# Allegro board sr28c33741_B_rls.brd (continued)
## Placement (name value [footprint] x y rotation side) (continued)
L263  2.7NH  [IND1005-HT0_6_HD]  59.09 13.08 90 top
L270  3.4NH  [IND1005-HT0_6_HD]  60.33 14.34 90 top
L271  0  [RES0402-HT0_4_HD]  61.44 14.73 0 top
L277  270NH  [INDP0402-HT0_55_HD]  63.98 15.95 0 top
L279  22NH  [IND0201-HT0_35_HD]  64.92 14.92 90 top
L301  56nH  [IND0201-HT0_33_HD]  60.02 34.46 0 top
L304  0  [RES0402-HT0_4_HD]  61.67 33.52 90 top
L305  2.5NH  [IND1005-HT0_6_HD]  60.92 34.59 90 top
L401  56nH  [IND0201-HT0_33_HD]  10.79 31.26 180 top
L404  2.2NH  [IND1005-HT0_6_HD]  8.88 32.8 180 top
L405  1e-006 uF  [CAP0402-HT0_55_HD]  8.88 33.57 180 top
L2200  0.47 uH  [IND2X1_6_PS1_55_HD]  26.07 58.91 0 top
L2201  0.47 uH  [IND2X1_6_PS1_55_HD]  26.73 60.96 0 top
L2202  0.47 uH  [IND2X1_6_PS1_55_HD]  24.07 61.76 0 top
L2203  1 uH  [IND2X1_6_PS1_4_HD]  23 52.29 270 top
L2204  1 uH  [IND2X1_6_PS1_4_HD]  26.83 53.45 0 top
L2205  1 uH  [IND2X1_6_PS1_4_HD]  25.98 56.86 0 top
L2270  1 uH  [IND2X1_6_PS1_4_HD]  8.54 59.75 270 top
L2300  0.47 uH  [IND2X1_6_PS1_55_HD]  32.66 43.26 90 top
L2301  0.47 uH  [IND2X1_6_PS1_55_HD]  42.2 43.65 0 top
L2302  0.47 uH  [IND2X1_6_PS1_55_HD]  39.06 45.94 90 top
L2303  0.47 uH  [IND2X1_6_PS1_55_HD]  36.29 45.92 90 top
L2304  0.47 uH  [IND2X1_6_PS1_55_HD]  34.24 45.91 90 top
L2400  1 uH  [IND2X1_6_PS1_4_HD]  16.4 60.73 90 top
L2440  0.47 uH  [IND2X1_6_PS1_55_HD]  42.45 40.41 270 top
L2501  4.7uH  [IND2_5X2_PS1_95_HD]  34.15 35.63 180 top
L2502  4.7uH  [IND2_5X2_PS1_95_HD]  39.41 35.49 0 top
L2503  4.7uH  [IND2_5X2_PS1_95_HD]  42.3 36.4 270 top
L2560  0.47 uH  [IND2X1_6_PS1_55_HD]  25.4 51.33 0 top
L2570  0.47 uH  [IND2X1_6_PS1_55_HD]  57.13 48.33 180 top
L3201  1PF  [CAP0201-HT0_33_HD]  26.91 36.75 270 top
L4041  3NH  [IND0201-HT0_35_HD]  46.76 35.01 270 top
L4042  8.2NH  [IND0201-HT0_35_HD]  45.76 32.95 90 top
L4046  0.039 uH  [IND0201-HT0_35_HD]  47.8 31.92 180 top
L4048  0.039 uH  [IND0201-HT0_35_HD]  47.79 30.49 180 top
L4051  3NH  [IND0201-HT0_35_HD]  56.38 27.93 90 top
L4052  8.2NH  [IND0201-HT0_35_HD]  58.11 27.19 270 top
L4056  0.039 uH  [IND0201-HT0_35_HD]  58.51 24.44 180 top
L4058  0.039 uH  [IND0201-HT0_35_HD]  58.74 23.02 180 top
L4061  9.1NH  [IND0201-HT0_35_HD]  60.09 27.54 0 top
L4062  9.1NH  [IND0201-HT0_35_HD]  60.74 25.13 90 top
L4066  0.039 uH  [IND0201-HT0_35_HD]  60.54 24.19 270 top
L4068  0.039 uH  [IND0201-HT0_35_HD]  59.83 22.99 0 top
L4071  9.1NH  [IND0201-HT0_35_HD]  53.35 31.76 0 top
L4072  9.1NH  [IND0201-HT0_35_HD]  51.8 30.1 90 top
L4076  0.039 uH  [IND0201-HT0_35_HD]  49.65 30.55 270 top
L4078  0.039 uH  [IND0201-HT0_35_HD]  48.96 30.56 270 top
L4120  1 uH  [IND2X1_6_PS1_4_HD]  62.63 49.42 90 top
L4150  82NH  [IND1005-HT0_6_HD]  60.66 57.45 180 top
L4160  82NH  [IND1005-HT0_6_HD]  58.93 56.99 90 top
L4600  1 uH  [IND2X1_6_PS1_4_HD]  8.99 20.66 0 top
L4610  0.12 uH  [IND0603_HD]  9.81 10.22 221 top
L4611  0.12 uH  [IND0603_HD]  8.93 4.72 170 top
L4670  18nH  [IND0603_SZ1_65X0_99-HT1_HD]  34.69 12.06 270 bottom
L4671  18nH  [IND0603_SZ1_65X0_99-HT1_HD]  39.59 12.06 270 bottom
L6292  0.47 uH  [IND0603-HT0_95_HD]  14.42 52.03 180 top
L6400  1 uH  [IND2X1_6_PS1_4_HD]  11.16 25.88 180 top
L6401  160nH  [IND0603_HD]  15.82 16.54 270 top
L6402  160nH  [IND0603_HD]  16.97 16.54 270 top
L7001  9.1NH  [IND0201-HT0_35_HD]  28.25 16.18 270 top
L7004  .5PF  [CAP0201-HT0_33_HD]  27.7 13.48 90 top
L7030  3.6NH  [IND0201-HT0_35_HD]  40.96 14.89 180 top
L7031  3.3 NH  [IND0201-HT0_35_HD]  39.09 15.37 270 top
L7051  .5PF  [CAP0201-HT0_33_HD]  10.14 28.87 90 top
L7056  .5PF  [CAP0201-HT0_33_HD]  9.88 31.86 180 top
L7111  18NH  [IND0201-HT0_35_HD]  53.52 19.72 180 top
L7113  0.027 uH  [IND0201-HT0_35_HD]  53.52 20.82 180 top
L7115  18NH  [IND0201-HT0_35_HD]  53.52 21.85 180 top
L7127  1NH  [IND0201-HT0_35_HD]  49.25 15.84 180 top
L7130  1.8PF  [CAP0201-HT0_33_HD]  49.44 17.09 180 top
L7131  8.2PF  [CAP0201-HT0_33_HD]  49.44 16.59 0 top
L7132  12NH  [IND0201-HT0_35_HD]  50.72 16.05 90 top
L7140  18NH  [IND0201-HT0_35_HD]  45.77 17.11 0 top
L7142  18NH  [IND0201-HT0_35_HD]  50.2 16.05 90 top
L7144  18NH  [IND0201-HT0_35_HD]  39.89 14.69 180 top
L7166  4.3NH  [IND0201-HT0_35_HD]  33.05 25.71 270 top
L7171  18NH  [IND0201-HT0_35_HD]  36.44 14.02 90 top
L7172  .5PF  [CAP0201-HT0_33_HD]  38.83 14.63 180 top
L7173  18NH  [IND0201-HT0_35_HD]  36.64 15.73 180 top
L7180  18NH  [IND0201-HT0_35_HD]  37.68 15.75 180 top
L7183  1NH  [IND0201-HT0_35_HD]  37.94 14.96 270 top
L7184  3NH  [IND0201-HT0_35_HD]  32.09 21.46 270 top
L7219  18NH  [IND0201-HT0_35_HD]  27.72 25.9 180 top
L7231  3.3PF  [CAP0201-HT0_33_HD]  47.69 24.33 270 top
L7232  0  [RES0201-HT0_28_HD]  46.98 24.18 0 top
L7233  15NH  [IND0201-HT0_35_HD]  43.18 20.03 90 top
L7236  6.2NH  [IND0201-HT0_35_HD]  43.93 20.2 0 top
L7237  100PF  [CAP0201-HT0_33_HD]  44.66 19.97 90 top
L7239  8.2NH  [IND0201-HT0_35_HD]  44.55 19.2 180 top
L7240  15NH  [IND0201-HT0_35_HD]  44.46 23.41 270 top
L7260  2.2PF  [CAP0201-HT0_33_HD]  48.2 25.28 270 top
L7262  0.047 uH  [IND0201-HT0_35_HD]  46.48 25.26 270 top
L7263  12NH  [IND0201-HT0_35_HD]  45.02 26.3 0 top
L7265  0.033 uH  [IND0201-HT0_35_HD]  45.93 27.01 180 top
L7267  8.2NH  [IND0201-HT0_35_HD]  47.38 26.76 180 top
L7268  0.047 uH  [IND0201-HT0_35_HD]  43.29 24.71 270 top
L7274  15NH  [IND0201-HT0_35_HD]  28.63 25.89 0 top
L7301  22NH  [IND0201-HT0_35_HD]  31.81 20.57 180 top
L7302  0  [RES0201-HT0_28_HD]  31.68 19.75 270 top
L7303  3.6NH  [IND0201-HT0_35_HD]  32.45 15.24 0 top
L7306  0  [RES0201-HT0_28_HD]  30.21 30.91 90 top
L7311  18NH  [IND0201-HT0_35_HD]  31.94 18.94 0 top
L7313  6.2NH  [IND0201-HT0_35_HD]  35.15 13.26 180 top
L7317  3.6NH  [IND0201-HT0_35_HD]  35.71 15.74 180 top
L7318  0  [RES0201-HT0_28_HD]  34.77 15.74 180 top
L7326  4.7NH  [IND0201-HT0_35_HD]  28.97 30.94 180 top
L7328  1.6NH  [IND0201-HT0_35_HD]  28.85 31.67 270 top
L7329  2.4NH  [IND0201-HT0_35_HD]  29.22 32.78 270 top
L7331  1NH  [IND0201-HT0_35_HD]  29.81 30.19 180 top
L7332  6.8NH  [IND0201-HT0_35_HD]  31.32 30.18 180 top
L7333  .9NH  [IND0201-HT0_35_HD]  28.88 29.97 180 top
L7334  2NH  [IND0201-HT0_35_HD]  29.73 29.2 90 top
L7335  6.8NH  [IND0201-HT0_35_HD]  26.77 29.1 180 top
L7336  1NH  [IND0201-HT0_35_HD]  26.1 29.76 90 top
L7350  18NH  [IND0201-HT0_35_HD]  39.83 22 180 top
L7352  9.1NH  [IND0201-HT0_35_HD]  40.59 21.69 270 top
L7354  9.1NH  [IND0201-HT0_35_HD]  39.83 18.65 0 top
L7367  1.5NH  [IND0201-HT0_35_HD]  28.63 28.18 90 top
L7368  2.7NH  [IND0201-HT0_35_HD]  28.11 29.69 90 top
L7371  3.3 NH  [IND0201-HT0_35_HD]  27.71 28.07 90 top
L7505  0.039 uH  [IND0201-HT0_35_HD]  16.05 24.76 270 top
L7516  4.7NH  [IND0201-HT0_35_HD]  22.67 23.63 270 top
L7525  22NH  [IND0201-HT0_35_HD]  42.65 31.6 0 top
L7601  3.9NH  [IND0201-HT0_35_HD]  18.77 28.3 0 top
L7603  .9NH  [IND0201-HT0_35_HD]  21.62 29.85 0 top
L7611  2.7NH  [IND0201-HT0_35_HD]  21.26 25.72 90 top
L7612  2.7NH  [IND0201-HT0_35_HD]  24.69 28.46 90 top
L7614  1.5NH  [IND0201-HT0_35_HD]  24.41 29.41 90 top
L7616  1NH  [IND0201-HT0_35_HD]  21.54 30.48 0 top
L7621  4.3NH  [IND0201-HT0_35_HD]  18.21 26.8 270 top
L7623  4.3NH  [IND0201-HT0_35_HD]  19.7 25.82 90 top
L7626  4.7NH  [IND0201-HT0_35_HD]  21.54 30.98 0 top
L7627  9.1NH  [IND0201-HT0_35_HD]  42.93 29.86 90 top
L7629  4.3NH  [IND0201-HT0_35_HD]  19.87 28.19 180 top
L7630  4.3NH  [IND0201-HT0_35_HD]  23.86 27.47 90 top
L7631  10NH  [IND0201-HT0_35_HD]  21.29 27.23 90 top
L7647  15NH  [IND0201-HT0_35_HD]  20.55 29.13 90 top
L7648  15NH  [IND0201-HT0_35_HD]  17.97 29.47 90 top
L7703  18NH  [IND0201-HT0_35_HD]  14.64 34.23 180 top
L7708  15NH  [IND0201-HT0_35_HD]  15.57 34.21 0 top
L7716  1NH  [IND0201-HT0_35_HD]  15.83 26.84 0 top
L7717  1NH  [IND0201-HT0_35_HD]  13.44 29.84 0 top
L7721  15NH  [IND0201-HT0_35_HD]  12.8 31.98 0 top
L7722  15NH  [IND0201-HT0_35_HD]  12.71 34.25 0 top
L7801  6.8NH  [IND0201-HT0_35_HD]  39.84 28.58 270 top
L7820  3NH  [IND0201-HT0_35_HD]  34.6 28.93 0 top
L7821  9.1NH  [IND0201-HT0_35_HD]  35.6 31.27 0 top
L7825  1NH  [IND0201-HT0_35_HD]  23.91 29.41 90 top
L7831  3.3 NH  [IND0201-HT0_35_HD]  38.98 31.02 270 top
L7832  1.8PF  [CAP0201-HT0_33_HD]  21.82 29.13 90 top
L7833  3.3 NH  [IND0201-HT0_35_HD]  36.76 30.34 90 top
L7834  15PF  [CAP0201-HT0_33_HD]  21.82 28.21 270 top
L8200  1uH  [IND2_5X2_PS1_95_HD]  25 17.05 180 top
L8201  1 uH  [IND2X1_6_PS1_4_HD]  19.93 18.77 270 top
L8501  9.1NH  [IND0201-HT0_35_HD]  24.86 24.59 270 top
L8502  8.2NH  [IND0201-HT0_35_HD]  23.73 24.03 180 top
L8503  7.5NH  [IND0201-HT0_35_HD]  22.49 25.87 180 top
L8504  6.2NH  [IND0201-HT0_35_HD]  20.61 31.81 0 top
L8516  2.2PF  [CAP0201-HT0_33_HD]  20.87 34.93 180 top
L8518  9.1NH  [IND0201-HT0_35_HD]  21.23 33.38 270 top
L8519  9.1NH  [IND0201-HT0_35_HD]  20.64 34.22 270 top
M001  -  [MECH0_7X4_5_HD]  48.15 46.18 90 top
M002  -  [MECH0_7X2_83_HD]  3.91 59.15 180 top
M003  -  [MECH0_7X2_83_HD]  4.21 53.9 180 top
M004  -  [MECH0_7X4_5_HD]  9.34 49.53 90 top
M005  -  [MECH0_7X2_83_HD]  17.12 49.53 90 top
M006  -  [MECH0_7X4_5_HD]  16.14 63.32 270 top
M007  -  [MECH0_7X4_5_HD]  22.84 63.32 90 top
M008  -  [MECH0_7X4_5_HD]  31.65 63.32 90 top
M009  -  [MECH0_7X4_5_HD]  38.65 63.32 90 top
M010  -  [MECH0_7X4_5_HD]  45.99 63.32 90 top
M011  -  [MECH0_7X2_83_HD]  44.05 37.26 0 top
M012  -  [MECH0_7X4_5_HD]  52.75 63.32 270 top
M013  -  [MECH0_7X2_83_HD]  39.92 33.33 270 top
M014  -  [MECH0_7X4_5_HD]  61.22 61.28 45 top
M015  -  [MECH0_7X4_5_HD]  8.99 63.32 270 top
M021  -  [MECH0_7X2_83_HD]  31.11 43.56 180 top
M022  -  [MECH0_7X2_83_HD]  31.11 37.61 180 top
M023  -  [MECH0_7X2_83_HD]  35.76 33.33 270 top
M024  -  [MECH0_7X4_5_HD]  64.09 53.58 0 top
M025  -  [MECH0_7X4_5_HD]  54.05 46.18 270 top
M026  -  [MECH0_7X2_83_HD]  44.05 42.41 0 top
M057  -  [MECH0_7X2_83_HD]  60.38 47.3 90 top
M060  -  [MECH0_7X4_5_HD]  24.84 47.43 270 top
M100  -  [MECH1_2X3_45EL2_76_HD]  5.88 11.91 0 bottom
M101  -  [MECH1_2X3_45EL2_76_HD]  3.49 11.91 0 bottom
M200  -  [MECH1_2X3_45EL2_76_HD]  62.9 11.91 0 bottom
M201  -  [MECH1_2X3_45EL2_76_HD]  65.29 11.91 0 bottom
M300  -  [MECH1_2X2_5_HD]  63.89 32.58 0 top
M301  -  [MECH2_2X5_09_HD]  6.34 29.92 143.4 top
M400  -  [MECH1_2X2_5_HD]  4.89 32.58 0 top
M401  -  [MECH2_2X5_09_HD]  62.43 29.92 216.6 top
M1001  -  [MECH1_8X4_52-HT0_93_HD]  9.03 13.24 90 top
M1002  -  [MECH1_2X2_5_HD]  14.39 12.87 90 top
M1003  -  [MECH2_4X1_1_HD]  29.09 10.8 180 top
M1004  -  [MECH2_4X1_1_HD]  36.54 10.8 0 top
M1005  -  [MECH1_8X4_52-HT0_93_HD]  47.02 13.38 270 top
M1006  -  [MECH1_8X4_52-HT0_93_HD]  55.82 13.46 90 top
M1007  -  [MECH2_4X1_1_HD]  65.29 11.38 90 top
M2000  -  [MECH1_8X4_52-HT0_93_HD]  7.65 66.34 0 top
M2001  -  [SPACER4C_TH_HD]  18.89 5.53 0 top
M3001  -  [MECH2_97X5_472MX_HD]  67.05 50.82 180 bottom
M3002  -  [MECH2_97X5_507_HD]  1.72 50.83 180 bottom
M3003  -  [MECH4_5X4_1_HD]  62.35 19.38 0 top
MK4520  -  [ACOUS1_6X2_5_1NP_PS0_72_P3_HD]  17.89 12.83 180 top
NOREF  -  [unnamed]  65.47 60.23 90 top
NOREF#2  -  [unnamed]  3.31 59.83 270 top
NOREF#3  -  [#2]  140.67 147.9 0 top
NOREF#4  -  [unnamed#3]  6.89 -0.47 180 top
NOREF#5  -  [#2]  34.39 51.03 0 top
NOREF#6  -  [unnamed#3]  4.73 7.14 350 top
NOREF#7  -  [unnamed#3]  71.39 0.03 0 top
NOREF#8  -  [unnamed#3]  5.06 8.96 350 top
NOREF#9  -  [unnamed#3]  49.52 66.53 180 top
NOREF#10  -  [#2]  104.39 92.53 180 top
NOREF#11  -  [#2]  -151.44 -87.34 0 top
NOREF#12  -  [#2]  -85.32 -85.29 0 top
NOREF#13  -  [unnamed#3]  13.83 4.71 41.4 top
NOREF#14  -  [#2]  1.89 -0.47 0 top
NOREF#15  -  [#2]  1.89 -0.47 0 top
NOREF#16  -  [unnamed]  15.54 1.78 352.5 top
NOREF#17  -  [unnamed#3]  47.39 0.03 0 top
NOREF#18  -  [unnamed#4]  54.95 12.43 0 top
NOREF#19  -  [unnamed]  3.31 34.83 270 top
NOREF#20  -  [unnamed]  14.19 69.43 180 top
NOREF#21  -  [#2]  34.39 92.53 180 top
NOREF#22  -  [unnamed#3]  67.09 51.66 0 top
NOREF#23  -  [#2]  1.89 -0.47 0 top
NOREF#24  -  [#2]  -494.61 217.03 0 top
NOREF#25  -  [unnamed]  40.44 6.62 90 top
NOREF#26  -  [unnamed#3]  67.09 17.53 0 top
NOREF#27  -  [unnamed]  42.64 68.83 180 top
NOREF#28  -  [#2]  1.89 -0.47 0 top
NOREF#29  -  [#2]  62.41 35.03 0 top
NOREF#30  -  [#2]  -489.55 -129.14 0 top
NOREF#31  -  [#2]  1.89 -0.47 0 top
NOREF#32  -  [#2]  104.39 51.03 0 top
NOREF#33  -  [#2]  34.39 92.53 180 top
NOREF#34  -  [unnamed#3]  65.39 0.03 0 top
NOREF#35  -  [unnamed#3]  1.89 144.03 180 top
NOREF#36  -  [#2]  -3.31 145.03 0 top
NOREF#37  -  [#2]  0.89 -5.47 0 top
NOREF#38  -  [unnamed#3]  5.76 10.47 180 top
NOREF#39  -  [unnamed]  65.47 35.23 90 top
NOREF#40  -  [#2]  104.39 92.53 180 top
NOREF#41  -  [unnamed#3]  1.69 17.53 0 top
NOREF#42  -  [#2]  -3.11 -1.47 0 top
NOREF#43  -  [#2]  104.39 51.03 0 top
NOREF#44  -  [unnamed#3]  1.69 51.66 90 top
NOREF#45  -  [unnamed#3]  1.89 -0.47 0 top
NOREF#46  -  [#2]  137.69 -5.47 90 top
NOREF#47  -  [unnamed#3]  53.39 0.03 0 top
NOREF#48  -  [unnamed#3]  136.89 144.03 180 top
NOREF#49  -  [unnamed#3]  60.49 59.48 0 top
NOREF#50  -  [unnamed#3]  131.89 -0.47 0 top
NOREF#51  -  [unnamed#3]  6.89 144.03 180 top
NOREF#52  -  [unnamed#3]  136.89 -0.47 0 top
NOREF#53  -  [unnamed#3]  59.39 0.03 0 top
NOREF#54  -  [unnamed#3]  131.89 -0.47 0 bottom
NOREF#55  -  [unnamed#3]  71.39 0.03 180 bottom
NOREF#56  -  [unnamed#3]  6.25 4.66 0 bottom
NOREF#57  -  [unnamed#3]  6.89 -0.47 0 bottom
NOREF#58  -  [unnamed#3]  59.39 0.03 180 bottom
NOREF#59  -  [unnamed#3]  47.39 0.03 180 bottom
NOREF#60  -  [unnamed#3]  6.89 144.03 0 bottom
NOREF#61  -  [unnamed#3]  63.8 65.18 0 bottom
NOREF#62  -  [unnamed#3]  53.39 0.03 180 bottom
NOREF#63  -  [unnamed#3]  65.39 0.03 180 bottom
Q1020  -  [SOT0_8X1_2RB_PS0_8-HT0_55_P3_HD]  44.99 50.92 270 bottom
Q2031  -  [SOT0_8X1_2RB_PS0_8-HT0_55_P3_HD]  16.31 53.03 0 top
Q2032  -  [SOT0_8X1_2RB_PS0_8-HT0_55_P3_HD]  4.88 67.58 0 top
Q5500  -  [BGA1_5SQ_B0_3_PS0_5_P9_HD]  13.16 60.37 0 top
Q6268  -  [DFN2SQ_PS0_65_P8_HD]  34.24 6.38 0 bottom
R101  0  [RES0201-HT0_28_HD]  12.99 11.31 180 top
R104  0  [RES0201-HT0_28_HD]  12.99 10.81 0 top
R109  1K  [RES0201-HT0_28_HD]  9.25 11.79 90 top
R130  100K  [RES0201-HT0_28_HD]  27.59 11.86 0 bottom
R131  10K  [RES0201-HT0_28_HD]  27.53 12.58 270 bottom
R201  0  [RES0201-HT0_28_HD]  56.03 20.55 270 top
R204  0  [RES0201-HT0_28_HD]  57.36 20.53 90 top
R210  100K  [RES0201-HT0_28_HD]  54.46 13.14 90 bottom
R211  10K  [RES0201-HT0_28_HD]  53.42 13.14 270 bottom
R215  1K  [RES0201-HT0_28_HD]  63.34 15.09 270 top
R230  100K  [RES0201-HT0_28_HD]  48.05 13.06 90 bottom
R231  10K  [RES0201-HT0_28_HD]  47.01 13.06 270 bottom
R280  1K  [RES0201-HT0_28_HD]  64.08 16.62 180 top
R300  0  [RES0201-HT0_28_HD]  60.25 33.49 270 top
R400  0  [RES0201-HT0_28_HD]  10.59 31.97 90 top
R500  47K  [RES0201-HT0_28_HD]  32.54 10.14 225 bottom
R510  5mohm  [RES0805-HT0_4_HD]  11 61.97 180 top
R519  10K  [RES0201-HT0_28_HD]  6.38 62.48 0 top
R520  100K  [RES0201-HT0_28_HD]  28.13 50.5 270 top
R1003  100  [RES0201-HT0_28_HD]  33.28 47.46 180 top
R1004  100  [RES0201-HT0_28_HD]  30.4 62.41 0 top
R1005  10K  [RES0201-HT0_28_HD]  56.91 55.68 180 top
R1006  10K  [RES0201-HT0_28_HD]  56.06 57.89 90 top
R1007  2.2K  [RES0201-HT0_28_HD]  42.42 49.84 270 top
R1011  240 ohm  [RES0201-HT0_28_HD]  40.79 60.87 90 top
R1021  470K  [RES0201-HT0_28_HD]  45.01 49.01 180 bottom
R1023  10K  [RES0201-HT0_28_HD]  46.24 51.52 180 bottom
R1031  2.2K  [RES0201-HT0_28_HD]  56.76 53.36 180 top
R1032  2.2K  [RES0201-HT0_28_HD]  56.76 53.86 180 top
R1033  2.2K  [RES0201-HT0_28_HD]  29.42 61.71 90 top
R1035  2.2K  [RES0201-HT0_28_HD]  55.67 62.3 270 top
R1036  2.2K  [RES0201-HT0_28_HD]  56.17 62.3 270 top
R1037  2.2K  [RES0201-HT0_28_HD]  13.44 22.88 180 top
R1038  2.2K  [RES0201-HT0_28_HD]  13.43 22.37 180 top
R1039  2.2K  [RES0201-HT0_28_HD]  26.06 64.46 180 top
R1040  2.2K  [RES0201-HT0_28_HD]  26.06 63.95 180 top
R1048  2.2K  [RES0201-HT0_28_HD]  18.5 64.28 270 top
R1049  2.2K  [RES0201-HT0_28_HD]  18 64.28 270 top
R1050  2.2K  [RES0201-HT0_28_HD]  7 60.56 270 top
R1051  2.2K  [RES0201-HT0_28_HD]  6.18 60.3 0 top
R1052  2.2K  [RES0201-HT0_28_HD]  12.66 68.94 0 top
R1053  2.2K  [RES0201-HT0_28_HD]  13.57 68.94 180 top
R1127  10K  [RES0201-HT0_28_HD]  26.85 66.08 90 top
R1128  10K  [RES0201-HT0_28_HD]  26.35 66.08 90 top
R1129  10K  [RES0201-HT0_28_HD]  27.35 66.08 270 top
R1130  10K  [RES0201-HT0_28_HD]  25.85 65.17 90 top
R1131  0  [RES0201-HT0_28_HD]  26.85 65.17 270 top
R1132  0  [RES0201-HT0_28_HD]  26.35 65.17 270 top
R1171  6.04K  [RES0201-HT0_28_HD]  38.3 60.65 0 top
R1172  6.04K  [RES0201-HT0_28_HD]  39.02 60.79 270 top
R1173  3.01K  [RES0201-HT0_28_HD]  30.21 48.09 270 top
R1524  0  [RES0201-HT0_28_HD]  24.79 11.19 0 bottom
R1526  0  [RES0201-HT0_28_HD]  24.79 12.25 0 bottom
R1527  0  [RES0201-HT0_28_HD]  21.21 13.78 0 top
R1528  0  [RES0201-HT0_28_HD]  19.38 13.17 270 top
R1529  0  [RES0201-HT0_28_HD]  25.5 13.94 270 top
R1530  0  [RES0201-HT0_28_HD]  20.09 14.01 0 top
R1531  0  [RES0201-HT0_28_HD]  23.98 13.94 270 top
R1600  0  [RES0201-HT0_28_HD]  42.56 54.98 0 top
R1603  240 ohm  [RES0201-HT0_28_HD]  55.2 60.89 180 top
R1605  240 ohm  [RES0201-HT0_28_HD]  55.2 60.37 180 top
R2015  0  [RES0201-HT0_28_HD]  21.1 61.27 90 top
R2016  10K  [RES0201-HT0_28_HD]  19.59 62.28 90 top
R2017  0  [RES0201-HT0_28_HD]  18.56 50.6 90 top
R2018  100K  [RES0201-HT0_28_HD]  16.91 51.96 180 top
R2019  0  [RES0201-HT0_28_HD]  9.07 68.98 0 top
R2020  100K  [RES0201-HT0_28_HD]  9.79 69.03 270 top
R2400  10K  [RES0201-HT0_28_HD]  15.15 55.94 270 top
R2401  1K  [RES0201-HT0_28_HD]  29.64 50.52 90 top
R2402  1K  [RES0201-HT0_28_HD]  29.14 50.52 90 top
R2403  39Kohm  [RES0201-HT0_26_HD]  14.43 56.42 180 top
R2406  243K  [RES0201-HT0_28_HD]  13.71 58.6 270 top
R2410  1MEG  [RES0201-HT0_28_HD]  14.34 59.77 90 top
R2418  0  [RES0201-HT0_28_HD]  13.42 39.33 0 top
R2453  10K  [RES0201-HT0_28_HD]  21.1 62.18 90 top
R2455  0  [RES0201-HT0_28_HD]  27.6 50.75 90 top
R3001  0  [RES0201-HT0_28_HD]  23.71 36.33 90 top
R3002  0  [RES0201-HT0_28_HD]  24.71 36.33 90 top
R3102  0  [RES0201-HT0_28_HD]  25.21 36.33 270 top
R3104  0  [RES0201-HT0_28_HD]  22.65 35.78 90 top
R3201  0  [RES0201-HT0_28_HD]  26.96 35.78 90 top
R3202  22PF  [CAP0201-HT0_33_HD]  26.46 35.78 270 top
R3301  51.1  [RES0201-HT0_28_HD]  26.36 36.75 270 top
R4002  0  [RES0201-HT0_28_HD]  57.27 37.14 270 top
R4003  0  [RES0201-HT0_28_HD]  51.57 34.38 180 top
R4006  51.1  [RES0201-HT0_28_HD]  57.29 35.39 180 top
R4009  33  [RES0201-HT0_28_HD]  52.08 36.68 0 top
R4010  51K  [RES0201-HT0_28_HD]  57.29 35.91 180 top
R4044  51.1  [RES0201-HT0_28_HD]  46.84 31.36 180 top
R4045  18  [RES0201-HT0_28_HD]  46.14 32.02 270 top
R4049  51.1  [RES0201-HT0_28_HD]  51.64 31.31 90 top
R4054  51.1  [RES0201-HT0_28_HD]  57.07 24.66 0 top
R4055  18  [RES0201-HT0_28_HD]  57.03 25.85 180 top
R4059  51.1  [RES0201-HT0_28_HD]  54.42 31.51 0 top
R4060  0  [RES0201-HT0_28_HD]  59.61 28.07 180 top
R4061  0  [RES0201-HT0_28_HD]  59.57 25.36 0 top
R4064  51.1  [RES0201-HT0_28_HD]  59.82 23.63 180 top
R4065  18  [RES0201-HT0_28_HD]  57.03 25.34 180 top
R4070  0  [RES0201-HT0_28_HD]  54.27 32.26 0 top
R4073  0  [RES0201-HT0_28_HD]  51.3 29.64 90 top
R4074  51.1  [RES0201-HT0_28_HD]  50.39 31.36 270 top
R4075  18  [RES0201-HT0_28_HD]  51.14 31.3 90 top
R4081  82  [RES0201-HT0_28_HD]  56.91 31.93 270 top
R4084  0  [RES0201-HT0_28_HD]  57.93 30.37 270 top
R4085  0  [RES0201-HT0_28_HD]  48.67 32.59 180 top
R4092  82  [RES0201-HT0_28_HD]  52.48 32.01 90 top
R4100  100K  [RES0201-HT0_28_HD]  57.73 52.64 0 top
R4120  100K  [RES0201-HT0_28_HD]  59.88 51.63 90 top
R4150  1K  [RES0201-HT0_28_HD]  60.76 58.6 180 top
R4151  100  [RES0201-HT0_28_HD]  60.76 58.09 180 top
R4152  0  [RES0201-HT0_28_HD]  59.55 61.09 90 top
R4155  2K  [RES0201-HT0_28_HD]  59.33 59.38 0 top
R4160  1K  [RES0201-HT0_28_HD]  57.84 58.65 90 top
R4161  100  [RES0201-HT0_28_HD]  58.07 57.94 0 top
R4162  0  [RES0201-HT0_28_HD]  59.05 61.09 90 top
R4211  0  [RES0201-HT0_28_HD]  54.81 40.6 0 top
R4212  100K  [RES0201-HT0_28_HD]  55.91 40.6 180 top
R4213  10K  [RES0201-HT0_28_HD]  53.51 44.54 270 top
R4214  0  [RES0201-HT0_28_HD]  59.38 51.63 90 top
R4215  0  [RES0201-HT0_28_HD]  53.83 45.29 180 top
R4216  0  [RES0201-HT0_28_HD]  54.01 44.55 90 top
R4217  0  [RES0201-HT0_28_HD]  53.82 43.35 180 top
R4218  0  [RES0201-HT0_28_HD]  57.51 46.97 0 top
R4250  10K  [RES0201-HT0_28_HD]  57.72 45.04 135 bottom
R4251  100K  [RES0201-HT0_28_HD]  58.47 45.76 90 bottom
R4256  100K  [RES0201-HT0_28_HD]  27.96 51.71 90 top
R4614  47K  [RES0201-HT0_28_HD]  9.95 15.79 0 top
R4615  0  [RES0201-HT0_28_HD]  13.26 19.67 180 top
R4618  47K  [RES0201-HT0_28_HD]  9.02 15.79 180 top
R5000  1MEG  [RES0201-HT0_28_HD]  57.07 58.28 0 top
R5001  1MEG  [RES0201-HT0_28_HD]  56.14 58.78 0 top
R5301  7.5K  [RES0201-HT0_28_HD]  58.7 62.08 270 top
R5321  100K  [RES0201-HT0_28_HD]  60.48 65.55 270 bottom
R5322  100K  [RES0201-HT0_28_HD]  61.02 65.56 270 bottom
R5500  470K  [RES0201-HT0_28_HD]  11.66 60.88 0 top
R5501  2  [RES0603-HT0_6_HD]  13.51 62.07 0 top
R5502  7.5K  [RES0201-HT0_28_HD]  58.28 64.33 180 top
R5801  100K  [RES0201-HT0_28_HD]  28.72 62.86 180 top
R5802  100K  [RES0201-HT0_28_HD]  28.72 62.36 180 top
R6110  0  [RES0201-HT0_28_HD]  64.29 60.29 90 top
R6115  0  [RES0201-HT0_28_HD]  51.8 41.36 180 top
R6130  2.2K  [RES0201-HT0_28_HD]  64.79 60.29 270 top
R6131  0  [RES0201-HT0_28_HD]  64.84 39.72 90 top
R6150  100  [RES0201-HT0_28_HD]  12.6 15.6 90 top
R6151  100  [RES0201-HT0_28_HD]  13.12 15.6 90 top
R6152  100  [RES0201-HT0_28_HD]  11.6 15.6 90 top
R6153  100  [RES0201-HT0_28_HD]  12.58 18.82 270 top
R6154  10K  [RES0201-HT0_28_HD]  10.98 21.8 90 top
R6155  100  [RES0201-HT0_28_HD]  12.1 15.6 90 top
R6180  49.9K  [RES0201-HT0_28_HD]  7.08 56.59 270 top
R6181  24Kohm  [RES0201-HT0_26_HD]  9.31 58.09 270 top
R6182  0  [RES0201-HT0_28_HD]  6.7 59.8 0 top
R6263  0  [RES0201-HT0_28_HD]  13.3 55.27 90 top
R6264  0  [RES0201-HT0_28_HD]  12.51 55.86 0 top
R6266  2.2K  [RES0201-HT0_28_HD]  31.9 5.76 270 bottom
R6267  2.2K  [RES0201-HT0_28_HD]  34.64 8.63 90 bottom
R6268  100  [RES0201-HT0_28_HD]  13.05 53.06 90 top
R6402  47K  [RES0201-HT0_28_HD]  9.46 21.91 0 top
R7050  0  [RES0201-HT0_28_HD]  10.85 29.09 0 top
R7108  0  [RES0201-HT0_28_HD]  51.67 24.76 0 top
R7120  270  [RES0201-HT0_28_HD]  47.41 16.96 90 top
R7121  18  [RES0201-HT0_28_HD]  47.92 16.96 270 top
R7122  270  [RES0201-HT0_28_HD]  48.46 16.96 270 top
R7153  0  [RES0201-HT0_28_HD]  32.09 23.93 90 top
R7156  0  [RES0201-HT0_28_HD]  39.81 23.74 0 top
R7176  270  [RES0201-HT0_28_HD]  39.83 17.48 0 top
R7177  0  [RES0201-HT0_28_HD]  40.77 17.48 0 top
R7178  270  [RES0201-HT0_28_HD]  41.68 17.47 180 top
R7200  0  [RES0201-HT0_28_HD]  25.53 23.52 270 top
R7201  0  [RES0201-HT0_28_HD]  25.94 26.44 90 top
R7307  33PF  [CAP0201-HT0_33_HD]  30.21 31.37 270 top
R7314  12NH  [IND0201-HT0_35_HD]  33.42 15.23 0 top
R7315  0  [RES0201-HT0_28_HD]  33.66 15.74 180 top
R7316  0  [RES0201-HT0_28_HD]  33.2 15.74 0 top
R7600  33PF  [CAP0201-HT0_33_HD]  20.74 25.73 90 top
R7620  51.1  [RES0201-HT0_28_HD]  19.2 25.82 270 top
R7701  100PF  [CAP0201-HT0_33_HD]  16.54 26.21 90 top
R7706  100PF  [CAP0201-HT0_33_HD]  18.38 31.97 90 top
R7710  100PF  [CAP0201-HT0_33_HD]  17.04 29.24 90 top
R7715  100PF  [CAP0201-HT0_33_HD]  16.02 25.99 90 top
R7718  100PF  [CAP0201-HT0_33_HD]  13.45 30.62 90 top
R7720  100PF  [CAP0201-HT0_33_HD]  12.94 31.24 90 top
R7723  100PF  [CAP0201-HT0_33_HD]  13.67 34.25 0 top
R7730  0  [RES0201-HT0_28_HD]  14.92 30.67 90 top
R7731  0  [RES0201-HT0_28_HD]  14.34 29.68 270 top
R7800  15PF  [CAP0201-HT0_33_HD]  40.6 28.33 180 top
R8201  1  [RES0201-HT0_28_HD]  21.8 16.56 90 top
R8500  0  [RES0201-HT0_28_HD]  24.37 26.55 270 top
R8510  5.6K  [RES0201-HT0_28_HD]  23.93 25.1 270 top
RT515  -  [RES0201-HT0_33_HD]  16.84 62.49 0 top
RT516  -  [RES0201-HT0_33_HD]  15 41.12 180 top
RT517  -  [RES0201-HT0_33_HD]  9.43 64.31 180 top
RT1001  -  [RES0201-HT0_33_HD]  25.26 52.99 90 top
RT2401  -  [RES0201-HT0_33_HD]  53.33 29.75 180 top
RT6165  -  [RES0201-HT0_33_HD]  48.46 47.25 0 top
RT7149  -  [RES0201-HT0_33_HD]  50.19 24.2 0 top
RT7199  -  [RES0201-HT0_33_HD]  39.81 24.24 180 top
SH1  -  [SHIELD_SND_BST_SM88C42469]  11.05 21.05 0 top
SH2  -  [SHIELD_WTR_SM88C42466]  22.23 30.8 0 top
SH3  -  [SHIELD_OVP_SM88C46177]  15.83 38.79 0 top
SH4  -  [SHIELD_QET_SM88C42471]  22.52 18.29 0 top
SH5  -  [SHIELD_DRX_HB_SM88C42467]  38.71 29.99 0 top
SH6  -  [SHIELD_MBHB_PA_SM88C42472]  36.75 19.54 0 top
SH7  -  [SHIELD_WIFI_SM88C42468]  53.24 30.25 0 top
SH8  -  [SHIELD_LB_PA_SM88C42473]  48.45 21.45 0 top
TP4101  -  [TPSM0_175CNG_HD]  57.07 54.3 0 top
TP4102  -  [TPSM0_175CNG_HD]  57.57 55.48 0 top
TP4103  -  [TPSM0_175CNG_HD]  60.39 57.16 180 bottom
TP4104  -  [TPSM0_175CNG_HD]  62.24 56.39 180 bottom
TP4105  -  [TPSM0_175CNG_HD]  60.72 57.15 180 bottom
TP_BA_N  -  [TPSM0_175CNG_HD]  22.91 43.33 0 top
TP_BASE_BAT_NEG  -  [TPSM1_27CAU_HD]  14.78 63.24 180 bottom
TP_BASE_BAT_POS  -  [TPSM1_27CAU_HD]  11.38 63.1 180 bottom
TP_BB_CLK1  -  [TPSM0_175CNG_HD]  32.17 51.5 180 bottom
TP_BOOT_CONFIG3  -  [TPSM0_175CNG_HD]  35.54 48.91 0 top
TP_CDC_32KHZ  -  [TPSM0_38CAU_HD]  12.15 50.17 0 top
TP_CDC_DEBUG  -  [TPSM0_38CAU_HD]  14.22 53.01 270 top
TP_CDC_RST  -  [TPSM0_38CAU_HD]  13.63 48.66 0 top
TP_DISP_PWR_EN  -  [TPSM0_175CNG_HD]  58.24 61.33 0 top
TP_DISP_V1_EN  -  [TPSM0_175CNG_HD]  61.72 62.13 0 top
TP_FAULT_N  -  [TPSM0_175CNG_HD]  27.21 43.53 0 top
TP_FORCEFLASH  -  [TPSM0_38CAU_HD]  46.09 50.32 180 bottom
TP_JTAG_RTCK  -  [TPSM0_38CAU_HD]  46.8 44.8 90 bottom
TP_KEY_DN  -  [TPSM0_38CAU_HD]  44.57 64.58 180 bottom
TP_NFC_GND_1  -  [TPSM0_38CAU_HD]  58.48 59.37 0 top
TP_NFC_GND_2  -  [TPSM0_38CAU_HD]  61.07 60.3 0 top
TP_NFC_ST21_TX1  -  [TPSM0_38CAU_HD]  61.72 57.45 0 top
TP_NFC_ST21_TX2  -  [TPSM0_38CAU_HD]  59.57 56.62 0 top
TP_OVP_FLAG_N  -  [TPSM0_38CAU_HD]  13.67 38.27 0 top
TP_PDMCLK  -  [TPSM0_38CAU_HD]  12.75 48.66 0 top
TP_PDMDATA  -  [TPSM0_38CAU_HD]  12.15 48.66 0 top
TP_PON_OUT  -  [TPSM0_175CNG_HD]  22.75 43.11 0 top
TP_PWR_KEY  -  [TPSM1_27CAU_HD]  23.49 64.08 180 bottom
TP_REF_CSNS_CS3  -  [TPSM0_175CNG_HD]  63.84 17.03 0 top
TP_RFFE1_CLK  -  [TPSM0_175CNG_HD]  24.82 42.16 0 top
TP_RFFE1_DATA  -  [TPSM0_175CNG_HD]  24.99 41.85 0 top
TP_RFFE2_CLK  -  [TPSM0_175CNG_HD]  23.37 42.16 180 top
TP_RFFE2_DATA  -  [TPSM0_175CNG_HD]  23.48 41.9 180 top
TP_RFFE3_CLK  -  [TPSM0_175CNG_HD]  25.35 41.84 180 top
TP_RFFE3_DATA  -  [TPSM0_175CNG_HD]  25.24 42.14 180 top
TP_RFFE4_CLK  -  [TPSM0_175CNG_HD]  24.15 42.15 180 top
TP_RFFE4_DATA  -  [TPSM0_175CNG_HD]  24.31 41.85 90 top
TP_RFFE5_CLK  -  [TPSM0_175CNG_HD]  24.66 41.83 0 top
TP_RFFE5_DATA  -  [TPSM0_175CNG_HD]  24.47 42.16 0 top
TP_SB_INT_N  -  [TPSM0_175CNG_HD]  7.95 38.28 270 top
TP_SB_RST  -  [TPSM0_175CNG_HD]  9.69 21.91 90 top
TP_SB_RX  -  [TPSM0_175CNG_HD]  9.06 36.71 270 top
TP_SB_SCK  -  [TPSM0_175CNG_HD]  8.25 37.83 270 top
TP_SB_TX  -  [TPSM0_175CNG_HD]  8.72 37.19 270 top
TP_SB_WS  -  [TPSM0_175CNG_HD]  9.39 36.26 270 top
TP_SLB  -  [TPSM0_38CAU_HD]  25.3 64.09 270 top
TP_SLEEP_CLK  -  [TPSM0_175CNG_HD]  22.77 48.35 0 top
TP_SLIMCLK  -  [TPSM0_175CNG_HD]  13.54 48.24 270 top
TP_SLIMDAT  -  [TPSM0_175CNG_HD]  12.84 51.09 270 top
TP_UART_GND  -  [TPSM0_38CAU_HD]  39.74 5.93 180 bottom
TP_UART_RX  -  [TPSM0_38CAU_HD]  39.74 7.18 0 bottom
TP_UART_TX  -  [TPSM0_38CAU_HD]  39.74 6.58 0 bottom
TP_USB_OVP_EN  -  [TPSM0_38CAU_HD]  13.11 38.26 0 top
U100  -  [LGA1_6X2_CTG0_6X1_PS0_4_P15_HD]  11.04 9.52 180 bottom
U200  -  [LGA1_6X2_CTG0_6X1_PS0_4_P15_HD]  57.17 18.77 0 top
U500  -  [CSF5X5US_SZ11_09X8_72_4G_PS1_3X1_45_P29_HD]  34.39 4.36 0 top
U519  -  [BGA1_46X1_47_B0_27_PS0_4-HT0_69_P9_HD]  5.82 61.39 90 top
U520  -  [QFN1_8X1_4_PS0_4-HT0_55_P10_HD]  28.78 49.07 180 top
U1001  -  [BGA11_1X10_5_PS0_35_P771_XD]  36.22 54.73 180 top
U1005  -  [BGA1_4X0_9_PO15432_B0_23_PS0_5-HT0_5_P5_HD]  56.92 56.78 90 top
U1600  -  [BGA13X11_5_B0_3_PS0_5_P254_HD]  48.88 54.75 270 top
U2000  -  [WLCSP5_05X5_64_PS0_35_P219_XD]  20.34 57.09 270 top
U2210  -  [BGA1_192X1_288_B0_25_PS0_4_P9_HD]  10.33 59.92 0 top
U2400  -  [WLCSP4_65X5_58_PS0_35_P196_XD]  37.11 40.93 180 top
U2401  -  [BGA1_66X2_26_B0_25_PS0_4_P20_HD]  15.05 38.8 90 top
U2560  -  [BGA2_02X1_31_B0_26_PS0_4_P15_HD]  24.37 49.17 270 top
U2570  -  [BGA2_02X1_31_B0_26_PS0_4_P15_HD]  58.26 50.49 90 top
U3100  -  [WLCSP5_79X4_43_B0_23_PS0_35_P180_XD]  24.96 32.89 180 top
U4000  -  [BGA4_07X3_97_B0_24_PS0_35_P116_XD]  54.69 34.68 180 top
U4040  -  [COUPLER0_65X0_5_PS0_39_P4_XD]  46.84 32.17 90 top
U4050  -  [COUPLER0_65X0_5_PS0_39_P4_XD]  57.91 25.24 90 top
U4060  -  [COUPLER0_65X0_5_PS0_39_P4_XD]  59.79 24.52 90 top
U4070  -  [COUPLER0_65X0_5_PS0_39_P4_XD]  50.52 30.47 0 top
U4080  -  [DFN1_7X2_CTG1_45X1_09_PS0_35_P11_XD]  56.29 30.39 90 top
U4081  -  [FLTR1X0_5_PS0_5_P4_HD]  55.96 31.99 180 top
U4090  -  [DFN1_7X2_CTG1_45X1_09_PS0_35_P11_XD]  48.68 34.14 0 top
U4091  -  [FLTR1X0_5_PS0_5_P4_HD]  50.66 33.08 90 top
U4100  -  [BGA4SQ_PS0_4_P64_HD]  60.33 54.17 270 top
U4120  -  [BGA1_21X1_31_B0_25_PS0_4_P9_HD]  60.9 49.56 180 top
U4200  -  [DFN4_2X4_CTG3_8X2_6_PS1_P9_HD]  56.55 43.23 90 top
U4250  -  [QFN2X1_5_PS0_5-HT0_6_P10_HD]  60.21 45.94 0 bottom
U4600  -  [BGA2_85X3_2_PS0_4_P36_HD]  9.63 17.57 90 top
U5000  -  [DFN1SQ_CTG0_48SQ_PS0_65_P5_HD]  57 59.89 180 top
U5300  -  [BGA0_96SQ_B0_32_PS0_5-HT0_63_P4_HD]  57.34 62.06 180 top
U5301  -  [BGA0_96SQ_B0_32_PS0_5-HT0_63_P4_HD]  61.49 63.57 270 top
U6110  -  [LGA2_5X3_PS0_5_P14_HD]  63.76 62.71 180 top
U6115  -  [LGA2_5X3_PS0_5_P14_HD]  51.73 43.39 180 top
U6130  -  [WLCSP0_78X1_18_B0_22_PS0_4_P5_HD]  64.03 39.43 0 top
U6140  -  [LGA2X2_5_PS0_65-HT1_P8_HD]  4.81 65.35 180 top
U6150  -  [DFN2_1X1_8_PS0_4_P10_HD]  12.58 17.21 180 top
U6180  -  [DFN2SQ_CTG1_6X0_9_PS0_5_P9_HD]  5.86 58.27 0 top
U6182  -  [BGA1_9X0_9_B0_23_PS0_5-HT0_5_P8_HD]  5.16 51.25 270 top
U6250  -  [WLCSP4_65X5_81_B0_27_PS0_4_P173_HD]  9.74 53.02 270 top
U6290  -  [BGA1_3X0_93_B0_2_PS0_4-HT0_4_P6_HD]  14.69 50.7 180 top
U6400  -  [BGA2_2884X2_4658_PS0_4_P30_HD]  11.17 23.54 270 top
U7100  -  [PA7_6X6_CTG24_PS0_44_P80_HD]  49.03 20.65 0 top
U7150  -  [PA8_6X6_5_CTG_PS0_44_P62_HD]  35.87 20.58 90 top
U7216  -  [BGA2_5SQ_B0_22_PS0_35_P24_XD]  27.64 24.27 0 top
U7230  -  [FLTR2X1_6_PS0_76X0_58_P9_HD]  43.92 21.73 90 top
U7500  -  [QFN2SQ_CTG0_98SQ_PS0_4-HT0_6_P15_HD]  17.6 24.44 90 top
U7510  -  [LGA1_6SQ_PS0_4_P12_XD]  20.83 24.21 180 top
U7520  -  [LGA1_6SQ_PS0_4_P12_XD]  41.18 29.74 180 top
U7701  -  [BGA2_5SQ_B0_22_PS0_35_P24_XD]  15.15 32.56 0 top
U8200  -  [WLCSP2_64X2_02_B0_22_PS0_35_P34_XD]  22.22 18.38 90 top
U8501  -  [LGA1_1X0_7-HT0_4_P6_HD]  22.85 24.93 180 top
VR510  -  [DIO1_6X0_8K1A2_HD]  8.99 64.22 180 bottom
VR1020  -  [DIO0_6X0_3BI_HD]  43.46 44.83 180 bottom
VR1021  -  [DIO0_6X0_3BI_HD]  44.3 44.64 270 bottom
VR1506  -  [DIO0_6X0_3BI_HD]  23.47 13.94 270 top
VR1507  -  [DIO0_6X0_3BI_HD]  20.09 13 0 top
VR1508  -  [DIO0_6X0_3BI_HD]  24.49 13.94 270 top
VR1509  -  [DIO0_6X0_3BI_HD]  20.19 12.26 90 top
VR1510  -  [DIO0_6X0_3BI_HD]  22.44 13.94 270 top
VR1511  -  [DIO1X0_6BI_HD]  25.75 12.11 90 bottom
VR1513  -  [DIO1X0_6BI_HD]  26.01 10.86 0 bottom
VR4251  -  [DIO0_6X0_3-HT0_32_HD]  58.38 44.39 315 bottom
VR4252  -  [DIO0_6X0_3-HT0_32_HD]  55.31 42 135 bottom
VR4253  -  [DIO0_6X0_3-HT0_32_HD]  54.63 42.7 135 bottom
VR4500  -  [DIO0_6X0_3-HT0_32_HD]  15.38 10.82 0 top
VR4501  -  [DIO0_6X0_3-HT0_32_HD]  14.67 11.05 270 top
VR4520  -  [DIO0_6X0_3-HT0_32_HD]  16.34 12.42 0 top
VR4521  -  [DIO0_6X0_3-HT0_32_HD]  17.72 14.54 180 top
VR4670  -  [DIO0_62X0_32-HT0_27_HD]  35.65 12.54 90 bottom
VR4671  -  [DIO0_62X0_32-HT0_27_HD]  38.63 12.54 90 bottom
WL_CMD_DATA_CH0  -  [TPSM0_38CAU_HD]  52.41 56.75 0 bottom
WL_CMD_DATA_CH1  -  [TPSM0_38CAU_HD]  52.69 56.16 0 bottom
Y2000  -  [XTAL1_6X1_2_PS1_03_P4_HD]  14.65 54.37 90 top

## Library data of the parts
C100 C105 C110 C132 C172 C200 C205 C210 C212 C213 C232 C272 C281 C501 C515 C516 C2004 C2262 C2271 C2272 C2274 C2277 C2278 C2281 C2405 C4004 C4005 C4032 C4501-C4503 C4522 C4523 C5306 C5310 C5316 C5322 C5369 C5374 C5382 C5387 C5504 C5507-C5513 C5515 C5520 C5524 C5531-C5539 C5541 C5542 C5549-C5551 C6153 C6400 C6630 C7102 C7105 C7109 C7112 C7114 C7150 C7155 C7157 C7161 C7199 C7215 C7219 C7230 C7234 C7235 C7241 C7267 C7269-C7271 C7274 C7280 C7285 C7290 C7500 C7501 C7505 C7702 C7707 C7712 C7750 C7751 C7755 C7768 L7237 R7701 R7706 R7710 R7715 R7718 R7720 R7723 = CAPACITOR: alternate symbols: (TOP:CAP0201-HT0_33_HD,CAP0201-HT0_33_JUMPER_90_HD;BOTTOM:CAP0201-HT0_33_HD,CAP0201-HT0_33_JUMPER_90_HD); part number: CAPACITOR-2113944E23
C102 C103 C202 C203 C518 C519 C521 C1005 C1007 C1080 C1104 C1130 C1131 C1604 C1615 C2001 C2003 C2018 C2020 C2108 C2333 C2334 C2398 C2420 C2512 C2562 C2572 C3002 C3016 C4011 C4026 C4083 C4085 C4093 C4095 C4101 C4105 C4130 C4215 C4506 C4520 C4600 C4601 C4603 C5001 C5307 C5311 C5317 C5323 C6110 C6115 C6130 C6140 C6180 C6183 C6184 C6269-C6271 C6401 C7101 C7104 C7152 C7162 C7218 C7273 C7753 C7767 C8500 = CAPACITOR: alternate symbols: (TOP:CAP0201-HT0_33_HD;BOTTOM:CAP0201-HT0_33_HD); part number: CAPACITOR-2113946U01
C112 = INDUCTOR: alternate symbols: (TOP:IND1005-HT0_6_HD;BOTTOM:IND1005-HT0_6_HD); part number: INDUCTOR-24014300058
C115 C215 = CAPACITOR: alternate symbols: (TOP:CAP0402-HT0_55_HD;BOTTOM:CAP0402-HT0_55_HD); part number: CAPACITOR-21014005208
C121 L223 = INDUCTOR: alternate symbols: (TOP:IND1005-HT0_6_HD;BOTTOM:IND1005-HT0_6_HD); part number: INDUCTOR-24014300135
C124 C224 = INDUCTOR: alternate symbols: (TOP:IND1005-HT0_6_HD;BOTTOM:IND1005-HT0_6_HD); part number: INDUCTOR-24014300022
C130 C133 C230 C233 C1020 C1021 C1023 C1511-C1516 C1532 C4047 C4057 C4067 C4077 C4156 C4166 C4608 C4609 C5620 C5680 C6181 C7106 C7107 C7110 C7154 C7158 C7165 C7170 C7173 C7300 C7327 C7330 C7332 C7335 C7385-C7390 C7510 C7511 C7607 C7608 C7610 C7613 C7617 C7620 C7622 C7644-C7648 C8503 C8505 C8516 R7307 R7600 = CAPACITOR: alternate symbols: (TOP:CAP0201-HT0_33_HD;BOTTOM:CAP0201-HT0_33_HD); part number: CAPACITOR-2113944E17
C140 C214 C240 C260 C406 L142 L171 L271 L304 = RESISTOR: alternate symbols: (TOP:RES0402-HT0_4_HD;BOTTOM:RES0402-HT0_4_HD); part number: RESISTOR-0613952R66
C141 = INDUCTOR: alternate symbols: (TOP:IND1005-HT0_6_HD;BOTTOM:IND1005-HT0_6_HD); part number: INDUCTOR-24014300034
C144 C241 L143 L218 = INDUCTOR: alternate symbols: (TOP:IND1005-HT0_6_HD;BOTTOM:IND1005-HT0_6_HD); part number: INDUCTOR-24014300046
C174 C275 C280 L124 L224 = CAPACITOR: alternate symbols: (TOP:CAP0201-HT0_33_HD;BOTTOM:CAP0201-HT0_33_HD); part number: CAPACITOR-2113944E03
C221 L405 = CAPACITOR: alternate symbols: (TOP:CAP0402-HT0_55_HD;BOTTOM:CAP0402-HT0_55_HD); part number: CAPACITOR-21014005020
C244 = CAPACITOR: alternate symbols: (TOP:CAP0402-HT0_55_HD;BOTTOM:CAP0402-HT0_55_HD); part number: CAPACITOR-21014005010
C250 C7141 C7895 C7896 = CAPACITOR: alternate symbols: (TOP:CAP0201-HT0_33_HD;BOTTOM:CAP0201-HT0_33_HD); part number: CAPACITOR-2113944E13
C261 L242 = CAPACITOR: alternate symbols: (TOP:CAP0402-HT0_55_HD;BOTTOM:CAP0402-HT0_55_HD); part number: CAPACITOR-21014005030
C264 = CAPACITOR: alternate symbols: (TOP:CAP0402-HT0_55_HD;BOTTOM:CAP0402-HT0_55_HD); part number: CAPACITOR-21014005006
C300 C400 C1517 C1518 C4060 C4063 C4070 C4073 C4504 C4505 C4521 C4524 C4670 C4672 C4674 C4675 C5370 C5500-C5503 C5514 C5516-C5519 C5521 C5528-C5530 C6154 C6155 C7351 C7355 C7368 C7369 C7520 C7521 C7526 = CAPACITOR: alternate symbols: (TOP:CAP0201-HT0_33_HD;BOTTOM:CAP0201-HT0_33_HD); part number: CAPACITOR-2113944E15
C303 = INDUCTOR: alternate symbols: (TOP:IND1005-HT0_6_HD;BOTTOM:IND1005-HT0_6_HD); part number: INDUCTOR-24014300028
C305 = CAPACITOR: alternate symbols: (TOP:CAP0402-HT0_55_HD;BOTTOM:CAP0402-HT0_55_HD); part number: CAPACITOR-21014005016
C402 = INDUCTOR: alternate symbols: (TOP:IND1005-HT0_6_HD;BOTTOM:IND1005-HT0_6_HD); part number: INDUCTOR-24014300025
C403 = CAPACITOR: alternate symbols: (TOP:CAP0402-HT0_55_HD;BOTTOM:CAP0402-HT0_55_HD); part number: CAPACITOR-21014005004
C502 C2434 = CAPACITOR: alternate symbols: (TOP:CAP0402-HT0_6_HD;BOTTOM:CAP0402-HT0_6_HD); part number: CAPACITOR-SC48C43287
C503 = CAPACITOR: alternate symbols: (TOP:CAP0402-HT0_55_HD;BOTTOM:CAP0402-HT0_55_HD); part number: CAPACITOR-21014048249
C504 C2431 C2433 C4606 C4607 C4671 C4673 = CAPACITOR: alternate symbols: (TOP:CAP0201-HT0_33_HD;BOTTOM:CAP0201-HT0_33_HD); part number: CAPACITOR-21014036004
C505-C508 C4007 C6272-C6277 C6289 C6290 C6295 C6296 = CAPACITOR: alternate symbols: (TOP:CAP0201-HT0_33_HD;BOTTOM:CAP0201-HT0_33_HD); part number: CAPACITOR-2113946U03
C509 C512-C514 = CAPACITOR: alternate symbols: (TOP:CAP0201-HT0_33_HD;BOTTOM:CAP0201-HT0_33_HD); part number: CAPACITOR-SC48C14435
C510 = CAPACITOR: alternate symbols: (TOP:CAP0201-HT0_33_HD,CAP0201-HT0_33_JUMPER_90_HD;BOTTOM:CAP0201-HT0_33_HD,CAP0201-HT0_33_JUMPER_90_HD); part number: CAPACITOR-2113944E23; room: P_POWER
C511 = CAPACITOR: alternate symbols: (TOP:CAP1_2X0_7_HD;BOTTOM:CAP1_2X0_7_HD); part number: CAPACITOR-21014029001; room: P_POWER
C517 C4002 C4003 C4006 C4008-C4010 C4019 C4020 C4023-C4025 C4027 = CAPACITOR: alternate symbols: (TOP:CAP0201-HT0_33_HD;BOTTOM:CAP0201-HT0_33_HD); part number: CAPACITOR-21014023001
C520 = CAPACITOR: alternate symbols: (TOP:CAP0201-HT0_33_HD;BOTTOM:CAP0201-HT0_33_HD); part number: CAPACITOR-2113945F01
C522 C523 = CAPACITOR: alternate symbols: (TOP:CAP0201-HT0_33_HD;BOTTOM:CAP0201-HT0_33_HD); part number: CAPACITOR-21014036006
C1001 = CAPACITOR: alternate symbols: (TOP:CAP0201-HT0_33_HD;BOTTOM:CAP0201-HT0_33_HD); part number: CAPACITOR-2113946U09
C1003 C1004 C8501 C8507 = CAPACITOR: alternate symbols: (TOP:CAP0201-HT0_33_HD;BOTTOM:CAP0201-HT0_33_HD); part number: CAPACITOR-2113944E08
C1022 C1024 = CAPACITOR: alternate symbols: (TOP:CAP0201-HT0_33_HD;BOTTOM:CAP0201-HT0_33_HD); part number: CAPACITOR-2113945F07
C1049 C1053 C1054 C1064 C1067 C1068 C1070 C1077 C1078 C1090-C1103 C1105 C1106 C1111 C1112 C1119-C1124 C1126-C1129 C1132 C1140 C1150-C1152 C1154-C1157 C1159 C1164 C1603 C1606 C1609-C1611 C1614 C1616-C1621 C1624 C1632 C1633 C2002 C2319 C2330-C2332 C2352-C2354 C2370 C2371 C2375 C2377 C2381-C2384 C2386 C2396 C2407 C2421 C4084 C4094 C4102 C4108 C4115 C4214 C5002 C6241-C6244 C6261-C6264 C6267 C6268 C8206 = CAPACITOR: alternate symbols: (TOP:CAP0201_HD;BOTTOM:CAP0201_HD); part number: CAPACITOR-21014004001
C1050-C1052 C1057-C1060 C1071 C1072 C1075 C1076 C1107-C1110 C1114-C1117 = CAPACITOR 3PIN 1GND: alternate symbols: (TOP:CAP1_2X0_9_P3_HD;BOTTOM:CAP1_2X0_9_P3_HD); part number: CAPACITOR 3PIN 1GND-21014088001
C1133 C1141 = CAPACITOR 3PIN 1GND: alternate symbols: (TOP:CAP1X0_5-HT0_5_P3_HD;BOTTOM:CAP1X0_5-HT0_5_P3_HD); part number: CAPACITOR 3PIN 1GND-21014052001
C1601 C1602 C1605 C1607 C1608 C1612 C1613 C4110 C4131 C6266 C6282 C6285 C6291 = CAPACITOR: alternate symbols: (TOP:CAP0402-HT0_55_HD;BOTTOM:CAP0402-HT0_55_HD); part number: CAPACITOR-2170282H06
C1622 C1623 C2403 C2410 C2560 C2561 C2570 C2571 = CAPACITOR: alternate symbols: (TOP:CAP0402-HT0_65_HD;BOTTOM:CAP0402-HT0_65_HD); part number: CAPACITOR-21014032002
C2000 C7100 C7151 C7160 = CAPACITOR: alternate symbols: (TOP:CAP0201-HT0_33_HD;BOTTOM:CAP0201-HT0_33_HD); part number: CAPACITOR-2113945E07
C2253-C2258 C2355-C2359 C2451 C2455 = CAPACITOR: alternate symbols: (TOP:CAP0402-HT0_55_HD;BOTTOM:CAP0402-HT0_55_HD); part number: CAPACITOR-21014109001
C2263 C2270 C2275 C2276 C2279 C2283-C2288 C2295 C2296 C2404 C2409 C2416 C2417 C2501 C2502 C2504 C2506-C2510 = CAPACITOR: alternate symbols: (TOP:CAP1_2X0_7_HD;BOTTOM:CAP1_2X0_7_HD); part number: CAPACITOR-21014029001
C2282 C4602 C4610 C6402 C6410 = CAPACITOR: alternate symbols: (TOP:CAP1_2X0_7_HD;BOTTOM:CAP1_2X0_7_HD); part number: CAPACITOR-SC48C51236
C2290-C2292 C2294 = CAPACITOR: alternate symbols: (TOP:CAP1_2X0_7_HD;BOTTOM:CAP1_2X0_7_HD); part number: CAPACITOR-21014033001
C2320 C2336 C2339 C2372 C2374 C2376 C2380 C2385 C6245 C6260 C6265 C6283 C6284 C6287 C6288 C6292 C6293 = CAPACITOR: alternate symbols: (TOP:CAP0402-HT0_55_HD;BOTTOM:CAP0402-HT0_55_HD); part number: CAPACITOR-21014028001
C2335 C2337 C2338 C2340 C2397 C6629 = CAPACITOR: alternate symbols: (TOP:CAP0201_HD;BOTTOM:CAP0201_HD); part number: CAPACITOR-21014108001
C2360-C2364 C2452 C2453 C2503 C2505 C2563 C2564 C2573 C2574 C8200 C8201 = CAPACITOR: alternate symbols: (TOP:CAP0603-HT0_6_HD;BOTTOM:CAP0603-HT0_6_HD); part number: CAPACITOR-21014059001
C2400 = CAPACITOR: alternate symbols: (TOP:CAP0603-HT1_HD;BOTTOM:CAP0603-HT1_HD); part number: CAPACITOR-21014019001
C2402 = CAPACITOR: alternate symbols: (TOP:CAP0402-HT0_55_HD;BOTTOM:CAP0402-HT0_55_HD); part number: CAPACITOR-2113743L51
C2408 = CAPACITOR: alternate symbols: (TOP:CAP0201-HT0_33_HD;BOTTOM:CAP0201-HT0_33_HD); part number: CAPACITOR-21014057001
C2412 C2422 = CAPACITOR: alternate symbols: (TOP:CAP0402-HT0_6_HD;BOTTOM:CAP0402-HT0_6_HD); part number: CAPACITOR-SC48C27030
C2418 = CAPACITOR: alternate symbols: (TOP:CAP0201-HT0_33_HD;BOTTOM:CAP0201-HT0_33_HD); part number: CAPACITOR-SC49A6N1G4
C2430 C2432 = CAPACITOR: alternate symbols: (TOP:CAP0201-HT0_33_HD;BOTTOM:CAP0201-HT0_33_HD); part number: CAPACITOR-21014090001
C3001 C3005 C3007 C3013 C3015 C4001 C4012 C4018 C4022 C4082 C4092 C7701 = CAPACITOR: alternate symbols: (TOP:CAP0402_1_2X0_7-HT0_65_HD;BOTTOM:CAP0402_1_2X0_7-HT0_65_HD); part number: CAPACITOR-21001124002
C3003 C3004 C3006 C3008-C3012 C3014 C3018 C3121-C3123 C3125 = CAPACITOR: alternate symbols: (TOP:CAP0201-HT0_33_HD;BOTTOM:CAP0201-HT0_33_HD); part number: CAPACITOR-2113946U01; room: P_WTR
C3102 C4086 C4087 C4096 C4097 C4152 C4162 C5505 C5506 = CAPACITOR: alternate symbols: (TOP:CAP0201-HT0_33_HD;BOTTOM:CAP0201-HT0_33_HD); part number: CAPACITOR-2113944E12
C3124 = CAPACITOR: alternate symbols: (TOP:CAP0201-HT0_33_HD;BOTTOM:CAP0201-HT0_33_HD); part number: CAPACITOR-2113946U05; room: P_WTR
C4000 = CAPACITOR: alternate symbols: (TOP:CAP0201_HD;BOTTOM:CAP0201_HD); part number: CAPACITOR-21014071001
C4013 C4015 C4016 C6286 C6406 = CAPACITOR: alternate symbols: (TOP:CAP0201-HT0_33_HD;BOTTOM:CAP0201-HT0_33_HD); part number: CAPACITOR-2113946U05
C4014 C4017 C4021 = CAPACITOR: alternate symbols: (TOP:CAP0402_1_2X0_7-HT0_65_HD;BOTTOM:CAP0402_1_2X0_7-HT0_65_HD); part number: CAPACITOR-21003097001
C4033 = CAPACITOR: alternate symbols: (TOP:CAP0201-HT0_33_HD;BOTTOM:CAP0201-HT0_33_HD); part number: CAPACITOR-2113944E18
C4034 C7003 R3202 = CAPACITOR: alternate symbols: (TOP:CAP0201-HT0_33_HD,CAP0201-HT0_33_JUMPER_90_HD;BOTTOM:CAP0201-HT0_33_HD,CAP0201-HT0_33_JUMPER_90_HD); part number: CAPACITOR-2113944E16
C4040 C4050 = CAPACITOR: alternate symbols: (TOP:CAP0201-HT0_33_HD;BOTTOM:CAP0201-HT0_33_HD); part number: CAPACITOR-2113944E10
C4043 C4053 C7515 L7231 = CAPACITOR: alternate symbols: (TOP:CAP0201-HT0_33_HD;BOTTOM:CAP0201-HT0_33_HD); part number: CAPACITOR-2113944E06
C4100 C4103 C4121 C4124 C4125 = CAPACITOR: alternate symbols: (TOP:CAP1_2X0_7_HD;BOTTOM:CAP1_2X0_7_HD); part number: CAPACITOR-21014032001
C4126 C6405 = CAPACITOR: alternate symbols: (TOP:CAP0402-HT0_55_HD;BOTTOM:CAP0402-HT0_55_HD); part number: CAPACITOR-2113945Y02
C4151 C4161 = CAPACITOR: alternate symbols: (TOP:CAP0201-HT0_33_HD;BOTTOM:CAP0201-HT0_33_HD); part number: CAPACITOR-21014081031
C4153 C4163 = CAPACITOR: alternate symbols: (TOP:CAP0201-HT0_33_HD;BOTTOM:CAP0201-HT0_33_HD); part number: CAPACITOR-2113945E02
C4154 = CAPACITOR: alternate symbols: (TOP:CAP0201-HT0_33_HD;BOTTOM:CAP0201-HT0_33_HD); part number: CAPACITOR-21014081029
C4155 C7216 C7217 C7264 C7760 C7761 C7867 L7130 L7832 = CAPACITOR: alternate symbols: (TOP:CAP0201-HT0_33_HD;BOTTOM:CAP0201-HT0_33_HD); part number: CAPACITOR-2113944E04
C4157 C4167 = CAPACITOR: alternate symbols: (TOP:CAP0201-HT0_33_HD;BOTTOM:CAP0201-HT0_33_HD); part number: CAPACITOR-2113944E22
C4159 C4169 C7312 C7353 L7232 L7302 L7306 L7318 R101 R104 R201 R204 R300 R400 R1131 R1132 R1524 R1526-R1531 R1600 R2015 R2017 R2019 R2418 R2455 R3001 R3002 R3102 R3104 R3201 R4002 R4003 R4060 R4061 R4070 R4073 R4084 R4085 R4152 R4162 R4211 R4214-R4218 R4615 R6110 R6115 R6131 R6182 R6263 R6264 R7050 R7108 R7153 R7156 R7177 R7200 R7201 R7315 R7316 R7730 R7731 R8500 = RESISTOR: alternate symbols: (TOP:RES0201-HT0_28_HD;BOTTOM:RES0201-HT0_28_HD); part number: RESISTOR-0613952Y66
C4165 = CAPACITOR: alternate symbols: (TOP:CAP0201-HT0_33_HD;BOTTOM:CAP0201-HT0_33_HD); part number: CAPACITOR-21014050213
C4604 C4605 C6403 C6404 C6408 = CAPACITOR: alternate symbols: (TOP:CAP0603-HT1_HD;BOTTOM:CAP0603-HT1_HD); part number: CAPACITOR-21014046373
C4618 C6407 = CAPACITOR: alternate symbols: (TOP:CAP0201-HT0_35_HD;BOTTOM:CAP0201-HT0_35_HD); part number: CAPACITOR-21014070001
C4790 = CAPACITOR: alternate symbols: (TOP:CAP0201-HT0_33_HD;BOTTOM:CAP0201-HT0_33_HD); part number: CAPACITOR-2113944E14; room: AUDIO
C5308 C5318 C5319 = CAPACITOR: alternate symbols: (TOP:CAP0201-HT0_33_HD,CAP0201-HT0_33_JUMPER_90_HD;BOTTOM:CAP0201-HT0_33_HD,CAP0201-HT0_33_JUMPER_90_HD); part number: CAPACITOR-2113944E23; room: DISPLAY
C5313 C5320 C5321 = CAPACITOR: alternate symbols: (TOP:CAP0201-HT0_33_HD;BOTTOM:CAP0201-HT0_33_HD); part number: CAPACITOR-2113944E15; room: DISPLAY
C6150 = CAPACITOR: alternate symbols: (TOP:CAP0201_HD;BOTTOM:CAP0201_HD); part number: CAPACITOR-21014004001; signal model: DEFAULT_CAPACITOR_1e+06pF_1_2
C6151 = CAPACITOR: alternate symbols: (TOP:CAP0201-HT0_33_HD;BOTTOM:CAP0201-HT0_33_HD); part number: CAPACITOR-2113946U01; signal model: DEFAULT_CAPACITOR_100000pF_1_2
C6152 = CAPACITOR: alternate symbols: (TOP:CAP0201-HT0_33_HD,CAP0201-HT0_33_JUMPER_90_HD;BOTTOM:CAP0201-HT0_33_HD,CAP0201-HT0_33_JUMPER_90_HD); part number: CAPACITOR-2113944E23; signal model: DEFAULT_CAPACITOR_100.000000pF_1_2
C7103 = CAPACITOR: alternate symbols: (TOP:CAP0402_1_2X0_7_HD;BOTTOM:CAP0402_1_2X0_7_HD); part number: CAPACITOR-SC48C50996
C7126 C7182 = CAPACITOR: alternate symbols: (TOP:CAP0201-HT0_33_HD;BOTTOM:CAP0201-HT0_33_HD); part number: CAPACITOR-21014600205
C7149 = CAPACITOR: alternate symbols: (TOP:CAP0201-HT0_33_HD,CAP0201-HT0_33_JUMPER_90_HD;BOTTOM:CAP0201-HT0_33_HD,CAP0201-HT0_33_JUMPER_90_HD); part number: CAPACITOR-2113944E23; room: P_HBPA
C7181 C7822 C7824 C7830 C7864 L7834 R7800 = CAPACITOR: alternate symbols: (TOP:CAP0201-HT0_33_HD;BOTTOM:CAP0201-HT0_33_HD); part number: CAPACITOR-2113944E14
C7238 C7700 C7705 L7004 L7051 L7056 L7172 = CAPACITOR: alternate symbols: (TOP:CAP0201-HT0_33_HD;BOTTOM:CAP0201-HT0_33_HD); part number: CAPACITOR-2113944E25
C7261 L7031 L7371 L7831 L7833 = INDUCTOR: alternate symbols: (TOP:IND0201-HT0_35_HD;BOTTOM:IND0201-HT0_35_HD); part number: INDUCTOR-24014052017
C7266 = CAPACITOR: alternate symbols: (TOP:CAP0201-HT0_33_HD;BOTTOM:CAP0201-HT0_33_HD); part number: CAPACITOR-2113944E02
C7326 C7371 C7625 L7260 L8516 = CAPACITOR: alternate symbols: (TOP:CAP0201-HT0_33_HD;BOTTOM:CAP0201-HT0_33_HD); part number: CAPACITOR-2113944E05
C7366 = INDUCTOR: alternate symbols: (TOP:IND0201-HT0_35_HD;BOTTOM:IND0201-HT0_35_HD); part number: INDUCTOR-24014052002
C7376 = CAPACITOR: alternate symbols: (TOP:CAP0201-HT0_33_HD;BOTTOM:CAP0201-HT0_33_HD); part number: CAPACITOR-2113944E27
C7517 = CAPACITOR: alternate symbols: (TOP:CAP0201-HT0_33_HD;BOTTOM:CAP0201-HT0_33_HD); part number: CAPACITOR-2113944E07
C7602 = INDUCTOR: alternate symbols: (TOP:IND0201-HT0_35_HD;BOTTOM:IND0201-HT0_35_HD); part number: INDUCTOR-24014052011
C7605 = INDUCTOR: alternate symbols: (TOP:IND0201-HT0_35_HD;BOTTOM:IND0201-HT0_35_HD); part number: INDUCTOR-24014052013
C7606 L7328 = INDUCTOR: alternate symbols: (TOP:IND0201-HT0_35_HD;BOTTOM:IND0201-HT0_35_HD); part number: INDUCTOR-24014052010
C7615 C7823 L7332 L7335 L7801 = INDUCTOR: alternate symbols: (TOP:IND0201-HT0_35_HD;BOTTOM:IND0201-HT0_35_HD); part number: INDUCTOR-24014052025
C7711 L7301 L7525 = INDUCTOR: alternate symbols: (TOP:IND0201-HT0_35_HD;BOTTOM:IND0201-HT0_35_HD); part number: INDUCTOR-24014052033
C7802 C8510 L3201 = CAPACITOR: alternate symbols: (TOP:CAP0201-HT0_33_HD;BOTTOM:CAP0201-HT0_33_HD); part number: CAPACITOR-2113944E01
C7835 C7863 L7368 L7611 L7612 = INDUCTOR: alternate symbols: (TOP:IND0201-HT0_35_HD;BOTTOM:IND0201-HT0_35_HD); part number: INDUCTOR-24014052015
C8202 C8204 C8205 = CAPACITOR: alternate symbols: (TOP:CAP0201_HD;BOTTOM:CAP0201_HD); part number: CAPACITOR-21014004001; room: P_5_149
C8203 = CAPACITOR: alternate symbols: (TOP:CAP0402_1_2X0_7-HT0_65_HD;BOTTOM:CAP0402_1_2X0_7-HT0_65_HD); part number: CAPACITOR-21003097001; room: P_5_149
C8208 = CAPACITOR: alternate symbols: (TOP:CAP0201-HT0_33_HD;BOTTOM:CAP0201-HT0_33_HD); part number: CAPACITOR-2113945E05; room: P_5_149
C8209 = CAPACITOR: alternate symbols: (TOP:CAP0402-HT0_65_HD;BOTTOM:CAP0402-HT0_65_HD); part number: CAPACITOR-21014032002; room: P_5_149
D350 D351 = TRANSIENT VOLTAGE SUPPRESSORS BIDIRECTIONAL: alternate symbols: (TOP:DIO0_6X0_3_PS0_525-HT0_33_HD;BOTTOM:DIO0_6X0_3_PS0_525-HT0_33_HD); part number: TRANSIENT VOLTAGE SUPPRESSORS BIDIRECTIONAL-SF68C43692
D352-D356 VR1020 VR1021 VR1506-VR1510 = TRANSIENT VOLTAGE SUPPRESSORS BIDIRECTIONAL: alternate symbols: (TOP:DIO0_6X0_3BI_HD;BOTTOM:DIO0_6X0_3BI_HD); part number: TRANSIENT VOLTAGE SUPPRESSORS BIDIRECTIONAL-48014258001
D500 = DIODE2 COMMON CATHODE_A1 A2 K3: alternate symbols: (TOP:DIO2SQ_PS1_3_P3_HD;BOTTOM:DIO2SQ_PS1_3_P3_HD); part number: DIODE2 COMMON CATHODE_A1 A2 K3-48014320001
D501-D509 D511 D512 D514 = DIODE ESD PROTECTION BIDIRECTIONAL 2PIN: alternate symbols: (TOP:DIO0_6X0_3BI_PS0_38_HD;BOTTOM:DIO0_6X0_3BI_PS0_38_HD); part number: DIODE ESD PROTECTION BIDIRECTIONAL 2PIN-48014322001
D510 D518 = ZENER_K1 A2: alternate symbols: (TOP:DIO1X0_6_PS0_65_HD;BOTTOM:DIO1X0_6_PS0_65_HD); part number: ZENER_K1 A2-48014217001; room: P_POWER
D513 = DIODE SCHOTTKY_K1 A2: alternate symbols: (TOP:DIO1X0_6K1A2_PS0_65_HD;BOTTOM:DIO1X0_6K1A2_PS0_65_HD); part number: DIODE SCHOTTKY_K1 A2-48014325001
D516 D517 = DIODE ESD PROTECTOR 2CATHODE: alternate symbols: (TOP:DIO0_6X0_3_PS0_4-HT0_32_HD;BOTTOM:DIO0_6X0_3_PS0_4-HT0_32_HD); part number: DIODE ESD PROTECTOR 2CATHODE-SF68C37390
